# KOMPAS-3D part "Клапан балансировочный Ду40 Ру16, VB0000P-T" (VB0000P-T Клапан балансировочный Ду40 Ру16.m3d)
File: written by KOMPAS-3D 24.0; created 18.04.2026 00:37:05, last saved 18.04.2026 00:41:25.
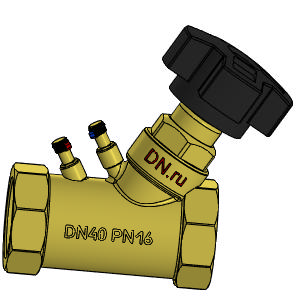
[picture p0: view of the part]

Document properties: Автор: tyuri; Полное имя файла: E:\Работа\Зайцев\АУТСОРС\Диман\Балансировка\VB0000P-T Клапан балансировочный DN.ru Ду15-50 Ру16\DN40\VB0000P-T Клапан балансировочный Ду40 Ру16.m3d

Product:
- Body: Тело 2  | qty 1
    Масса: 1.925365
- Part/product: Клапан балансировочный Ду40 Ру16  | designation VB0000P-T
    Масса: 0.98
    Раздел спецификации: Прочие изделия
    Примечание: D080-01095

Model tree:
1. Операция без истории:1

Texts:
  VB0000P-T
